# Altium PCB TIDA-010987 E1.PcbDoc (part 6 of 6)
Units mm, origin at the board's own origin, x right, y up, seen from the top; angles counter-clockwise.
Board outline 154.15 x 103.76 mm, 4 copper layers (5V, GND, MidSupply, -5V), stack 1.787 mm thick; 92 components, 52 nets, 1640 pads, 56 vias.
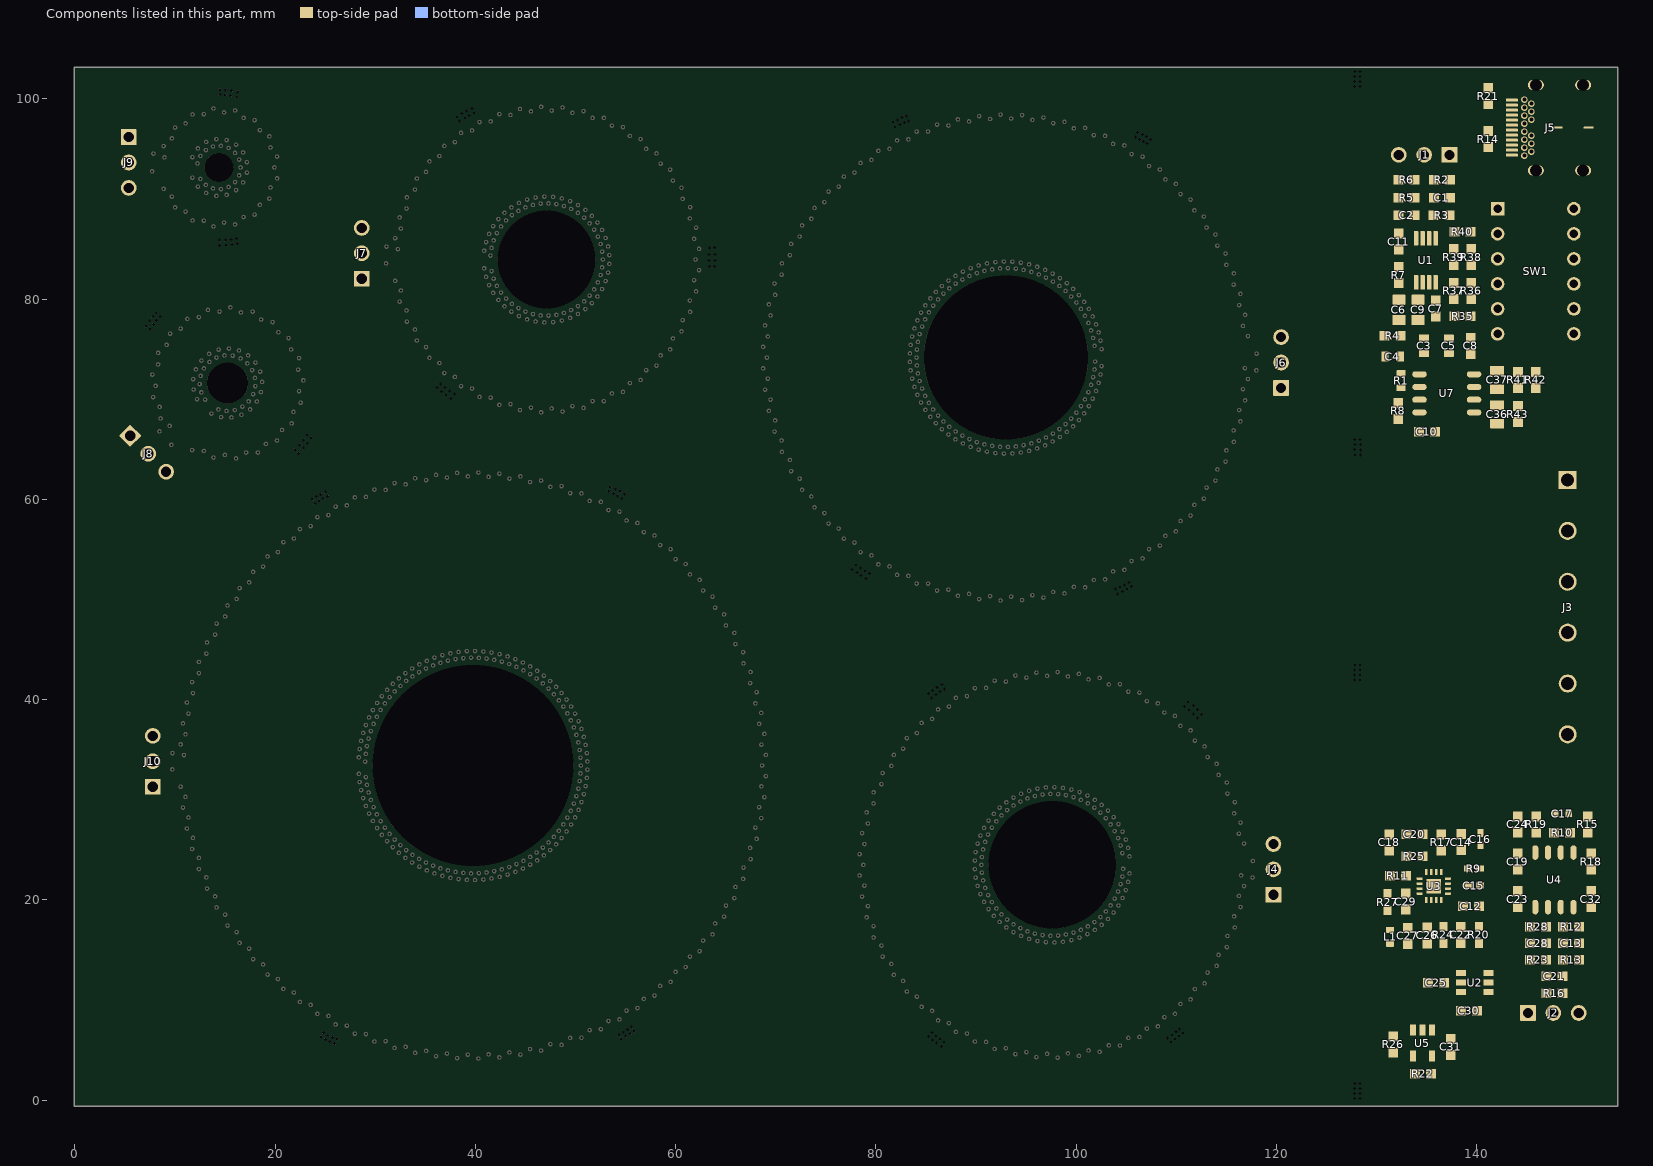
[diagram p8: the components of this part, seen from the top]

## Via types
v1: diameter 0.61, hole 0.203, 5V to -5V, tented both sides, 52 vias
v2: diameter 0.5, hole 0.2, 5V to -5V, tented both sides, 4 vias

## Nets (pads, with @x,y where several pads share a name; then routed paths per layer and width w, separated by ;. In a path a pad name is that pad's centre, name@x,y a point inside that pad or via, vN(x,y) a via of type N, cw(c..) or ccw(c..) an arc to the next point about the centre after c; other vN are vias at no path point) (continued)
copper on no net: (continued)
  -5V w0.1: 98.339,81.304 107.288,93.284 ; 98.392,66.22 106.644,54.089 ; 98.392,82.085 106.428,93.897 ccw(c106.644,94.216) 106.961,93.996 cw(c92.996,74.152) 108.064,93.172 cw(c108.364,92.931) 108.66,92.685 cw(c92.996,74.152) 109.963,91.499 ; 98.693,15.812 100.274,4.41 ; 98.693,31.173 100.221,42.194 ccw(c100.274,42.575) 100.655,42.518 cw(c97.628,23.493) 101.983,42.259 cw(c102.357,42.168) 102.73,42.07 cw(c97.628,23.493) 104.383,41.535 ; 98.95,67.501 ccw(c92.996,74.152) 99.245,67.778 cw(c99.514,68.053) 99.771,68.34 ccw(c92.996,74.152) 99.784,68.355 ccw(c100.028,68.653) 100.331,68.416 111.807,59.441 ; 98.95,80.804 ccw(c92.996,74.152) 98.642,81.067 cw(c98.339,81.304) 98.025,81.528 ccw(c92.996,74.152) 98.009,81.539 ccw(c97.686,81.748) 97.888,82.076 105.541,94.472 ; 98.987,16.537 101.248,4.963 ; 98.987,30.448 101.248,42.022 ; 99.072,66.728 108.12,55.672 ccw(c108.364,55.374) 108.064,55.133 cw(c92.996,74.152) 106.961,54.308 cw(c106.644,54.089) 106.324,53.875 cw(c92.996,74.152) 104.818,52.962 ; 99.072,81.577 108.364,92.931 ; 99.187,42.308 98.245,30.939 cw(c98.213,30.556) 98.596,30.513 cw(c97.628,23.493) 98.607,30.512 ccw(c98.987,30.448) 99.363,30.364 cw(c97.628,23.493) 99.744,30.257 ; 99.514,68.053 110.433,57.836 ; 99.514,80.252 110.433,90.469 ; 99.532,31.009 102.357,42.168 ; 99.704,67.294 109.963,56.806 ; 99.704,81.011 109.694,91.224 ccw(c109.963,91.499) 110.237,91.228 cw(c92.996,74.152) 111.177,90.222 cw(c111.43,89.932) 111.678,89.637 cw(c92.996,74.152) 112.753,88.241 ; 99.744,16.729 ccw(c97.628,23.493) 100.119,16.857 cw(c100.475,17.002) 100.823,17.167 ccw(c97.628,23.493) 100.833,17.172 ccw(c101.172,17.355) 101.364,17.022 107.068,7.142 ; 99.859,30.624 cw(c99.744,30.257) 100.108,30.132 cw(c97.628,23.493) 100.119,30.128 ccw(c100.475,29.983) 100.823,29.819 cw(c97.628,23.493) 101.172,29.63 ; 99.859,30.624 103.264,41.512 ; 100.028,68.653 ccw(c92.996,74.152) 100.27,68.978 cw(c100.486,69.296) 100.689,69.624 ccw(c92.996,74.152) 100.699,69.641 ccw(c100.886,69.977) 101.227,69.797 114.103,62.983 ; 100.028,79.652 ccw(c92.996,74.152) 99.771,79.965 cw(c99.514,80.252) 99.245,80.527 ccw(c92.996,74.152) 99.231,80.541 ccw(c98.95,80.804) 99.207,81.091 108.923,91.946 ; 100.284,67.914 111.138,58.624 ccw(c111.43,58.373) 111.177,58.083 cw(c92.996,74.152) 110.237,57.077 cw(c109.963,56.806) 109.686,56.539 cw(c92.996,74.152) 108.364,55.374 ; 100.284,80.391 111.43,89.932 ; 100.347,16.231 104.383,5.451 ; 100.347,30.754 104.248,41.174 ccw(c104.383,41.535) 104.742,41.396 cw(c97.628,23.493) 105.982,40.852 cw(c106.327,40.682) 106.669,40.505 cw(c97.628,23.493) 108.165,39.621 ; 100.475,17.002 105.212,6.203 ; 100.475,29.983 105.212,40.782 ; 100.486,69.296 113.033,61.161 ; 100.486,79.009 113.033,87.144 ; 100.807,68.583 112.753,60.064 ; 100.807,79.722 112.439,88.017 ccw(c112.753,88.241) 112.974,87.926 cw(c92.996,74.152) 113.723,86.77 cw(c113.92,86.44) 114.113,86.106 cw(c92.996,74.152) 114.924,84.542 ; 100.886,69.977 ccw(c92.996,74.152) 101.068,70.339 cw(c101.224,70.691) 101.366,71.049 ccw(c92.996,74.152) 101.373,71.068 ccw(c101.498,71.432) 101.865,71.314 115.74,66.874 ; 100.886,78.328 ccw(c92.996,74.152) 100.689,78.681 cw(c100.486,79.009) 100.27,79.327 ccw(c92.996,74.152) 100.258,79.343 ccw(c100.028,79.652) 100.331,79.889 111.807,88.864 ; 101.129,16.574 106.153,6.647 ccw(c106.327,6.303) 105.982,6.133 cw(c97.628,23.493) 104.742,5.589 cw(c104.383,5.451) 104.021,5.319 cw(c97.628,23.493) 102.357,4.817 ; 101.129,30.411 106.327,40.682 ; 101.172,17.355 ccw(c97.628,23.493) 101.509,17.563 cw(c101.826,17.782) 102.129,18.018 ccw(c97.628,23.493) 102.138,18.025 ccw(c102.428,18.278) 102.689,17.995 110.415,9.602 ; 101.224,70.691 115.008,64.892 ; 101.224,77.614 115.008,83.413 ; 101.269,69.295 113.588,62.06 ccw(c113.92,61.865) 113.723,61.535 cw(c92.996,74.152) 112.974,60.379 cw(c112.753,60.064) 112.527,59.752 cw(c92.996,74.152) 111.43,58.373 ; 101.269,79.01 113.92,86.44 ; 101.364,29.964 cw(c101.172,29.63) 101.5,29.429 cw(c97.628,23.493) 101.509,29.423 ccw(c101.826,29.203) 102.129,28.967 cw(c97.628,23.493) 102.428,28.707 ; 101.364,29.964 107.068,39.843 ; 101.498,71.432 ccw(c92.996,74.152) 101.613,71.82 cw(c101.705,72.194) 101.782,72.571 ccw(c92.996,74.152) 101.785,72.591 ccw(c101.844,72.971) 102.226,72.92 116.666,70.992 ; 101.498,76.873 ccw(c92.996,74.152) 101.366,77.256 cw(c101.224,77.614) 101.068,77.966 ccw(c92.996,74.152) 101.059,77.984 ccw(c100.886,78.328) 101.227,78.508 114.103,85.322 ; 101.666,70.045 114.924,63.763 ; 101.666,78.26 114.577,84.377 ccw(c114.924,84.542) 115.087,84.193 cw(c92.996,74.152) 115.621,82.924 cw(c115.757,82.564) 115.887,82.201 cw(c92.996,74.152) 116.411,80.519 ; 101.705,72.194 116.294,68.912 ; 101.705,76.111 116.294,79.393 ; 101.826,17.782 108.81,8.28 ; 101.826,29.203 108.81,38.705 ; 101.844,72.971 ccw(c92.996,74.152) 101.889,73.373 cw(c101.914,73.758) 101.923,74.143 118.031,74.152 120.037,73.843 ; 101.844,75.334 ccw(c92.996,74.152) 101.782,75.734 cw(c101.705,76.111) 101.613,76.485 ccw(c92.996,74.152) 101.608,76.504 ccw(c101.498,76.873) 101.865,76.991 115.74,81.431 ; 101.869,17.001 108.165,7.365 ; 101.869,29.984 107.955,39.298 ccw(c108.165,39.621) 108.485,39.407 cw(c97.628,23.493) 109.576,38.605 cw(c109.875,38.364) 110.17,38.116 cw(c97.628,23.493) 111.437,36.926 ; 101.914,73.758 116.853,73.096 ; 101.995,70.827 115.396,65.875 ccw(c115.757,65.741) 115.621,65.381 cw(c92.996,74.152) 115.087,64.112 cw(c114.924,63.763) 114.757,63.416 cw(c92.996,74.152) 113.92,61.865 ; 101.995,77.478 115.757,82.564 ; 102.254,71.635 116.411,67.786 ; 102.254,76.67 116.04,80.418 ccw(c116.411,80.519) 116.509,80.147 cw(c92.996,74.152) 116.811,78.803 cw(c116.882,78.425) 116.947,78.045 cw(c92.996,74.152) 117.166,76.297 ; 102.428,18.278 ccw(c97.628,23.493) 102.712,18.555 cw(c102.973,18.838) 103.218,19.135 ccw(c97.628,23.493) 103.224,19.144 ccw(c103.452,19.454) 103.769,19.235 113.143,12.735 ; 102.44,72.463 116.503,69.948 ccw(c116.882,69.88) 116.811,69.502 cw(c92.996,74.152) 116.509,68.158 cw(c116.411,67.786) 116.307,67.415 cw(c92.996,74.152) 115.757,65.741 ; 102.44,75.842 116.882,78.425 ; 102.552,73.305 117.166,72.008 ; 102.552,75 116.783,76.263 ccw(c117.166,76.297) 117.197,75.913 cw(c92.996,74.152) 117.238,75.226 101.914,74.547 ccw(c92.996,74.152) 101.887,74.951 ccw(c101.844,75.334) 102.226,75.385 116.666,77.313 ; 102.558,17.507 109.631,8.919 ccw(c109.875,8.622) 109.576,8.38 cw(c97.628,23.493) 108.485,7.578 cw(c108.165,7.365) 107.841,7.157 cw(c97.628,23.493) 106.327,6.303 ; 102.558,29.478 109.875,38.364 ; 102.973,18.838 111.866,11.093 ; 102.973,28.147 111.866,35.892 ; 103.186,18.086 111.437,10.059 ; 103.186,28.9 111.161,36.658 ccw(c111.437,36.926) 111.703,36.647 cw(c97.628,23.493) 112.592,35.627 cw(c112.831,35.325) 113.064,35.019 cw(c97.628,23.493) 114.04,33.581 ; 103.452,19.454 ccw(c97.628,23.493) 103.669,19.786 cw(c103.861,20.12) 104.035,20.463 ccw(c97.628,23.493) 104.04,20.473 ccw(c104.194,20.826) 104.551,20.681 115.12,16.388 ; 103.452,27.531 ccw(c97.628,23.493) 103.218,27.85 cw(c102.973,28.147) 102.712,28.431 ccw(c97.628,23.493) 102.704,28.439 ccw(c102.428,28.707) 102.689,28.99 110.415,37.383 ; 103.747,18.73 112.527,11.896 ccw(c112.831,11.66) 112.592,11.358 cw(c97.628,23.493) 111.703,10.338 cw(c111.437,10.059) 111.166,9.786 cw(c97.628,23.493) 109.875,8.622 ; 103.747,28.255 112.831,35.325 ; 103.861,20.12 114.233,14.507 ; 103.861,26.866 114.233,32.479 ; 104.194,20.826 ccw(c97.628,23.493) 104.333,21.197 cw(c104.448,21.564) 104.543,21.937 ccw(c97.628,23.493) 104.545,21.948 ccw(c104.619,22.326) 104.998,22.263 116.251,20.385 ; 104.194,26.16 ccw(c97.628,23.493) 104.035,26.522 cw(c103.861,26.866) 103.669,27.199 ccw(c97.628,23.493) 103.663,27.209 ccw(c103.452,27.531) 103.769,27.75 113.143,34.251 ; 104.234,19.432 114.04,13.404 ; 104.234,27.553 113.712,33.38 ccw(c114.04,33.581) 114.239,33.251 cw(c97.628,23.493) 114.883,32.061 cw(c115.051,31.714) 115.211,31.365 cw(c97.628,23.493) 115.849,29.748 ; 104.448,21.564 115.796,18.355 ; 104.448,25.421 115.796,28.63 ; 104.619,22.326 ccw(c97.628,23.493) 104.673,22.719 cw(c104.705,23.102) 104.715,23.487 117.663,23.493 119.71,23.038 117.66,23.878 ; 104.619,24.659 ccw(c97.628,23.493) 104.543,25.048 cw(c104.448,25.421) 104.333,25.789 ccw(c97.628,23.493) 104.33,25.799 ccw(c104.194,26.16) 104.551,26.304 115.12,30.597 ; 104.641,20.183 114.702,15.435 ccw(c115.051,15.271) 114.883,14.924 cw(c97.628,23.493) 114.239,13.734 cw(c114.04,13.404) 113.836,13.078 cw(c97.628,23.493) 112.831,11.66 ; 104.641,26.802 115.051,31.714 ; 104.705,23.102 116.48,22.453 ; 104.962,20.975 115.849,17.237 ; 104.962,26.01 115.485,29.623 ccw(c115.849,29.748) 115.971,29.383 cw(c97.628,23.493) 116.339,28.08 cw(c116.427,27.706) 116.507,27.329 cw(c97.628,23.493) 116.776,25.612 ; 105.195,21.797 116.051,19.364 ccw(c116.427,19.28) 116.339,18.905 cw(c97.628,23.493) 115.971,17.603 cw(c115.849,17.237) 115.721,16.874 cw(c97.628,23.493) 115.051,15.271 ; 105.195,25.188 116.427,27.706 ; 105.335,22.64 116.776,21.373 ; 105.335,24.346 116.394,25.57 ccw(c116.776,25.612) 116.815,25.229 cw(c97.628,23.493) 116.864,24.554 104.705,23.883 ccw(c97.628,23.493) 104.672,24.278 ccw(c104.619,24.659) 104.998,24.723 116.251,26.6 ; 116.427,19.28 ccw(c97.628,23.493) 116.73,20.991 ; 116.687,20.999 ccw(c116.776,21.373) 116.815,21.756 ccw(c97.628,23.493) 116.875,22.656 117.644,22.614 cw(c97.628,23.493) 117.623,22.229 ; 116.882,69.88 ccw(c92.996,74.152) 117.129,71.625 ; 117.095,71.63 ccw(c117.166,72.008) 117.197,72.392 ccw(c92.996,74.152) 117.246,73.304 118.016,73.27 cw(c92.996,74.152) 117.999,72.885 ; 118.028,74.537 120.037,73.843 ; 120.422,73.71 120.037,73.843 ; 120.472,73.66 120.431,73.716 120.377,73.791 120.037,73.843 ; 8.325,33.614 7.798,33.833 7.918,33.672 8.325,33.614

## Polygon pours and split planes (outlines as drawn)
-5V on -5V "-5V_-5V_P003" (solid, remove dead copper, pour order 3): 131.902,101.6 152.043,101.6 153.499,100.144 153.497,2.455 151.59,0.548 130.596,0.549 129.363,1.782 129.363,100.326 130.636,101.6
MidSupply on MidSupply "MIDSUPPLY_MIDSUPPLY_P002" (solid, remove dead copper, pour order 2): 131.902,101.6 152.043,101.6 153.499,100.144 153.497,2.461 151.584,0.548 130.596,0.549 129.363,1.782 129.363,100.326 130.636,101.6
GND on GND "GND_GND_P001" (solid, remove dead copper, pour order 1): 131.902,101.6 152.044,101.6 153.505,100.139 153.503,2.461 151.689,0.647 130.497,0.648 129.363,1.782 129.363,100.326 130.636,101.6
5V on 5V "5V_5V_P000" (solid, remove dead copper, pour order 0): 131.902,101.6 152.043,101.6 153.499,100.144 153.497,2.455 151.59,0.548 130.596,0.549 129.363,1.782 129.363,100.326 130.636,101.6

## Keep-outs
Keep-Out Layer:
  text ".Layer_Name" at 18.111,-20.282 h1.52

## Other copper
5V:
  text ".Layer_Name" at 18.111,-20.282 h1.52
-5V:
  text ".Layer_Name" at 18.111,-20.282 h1.52

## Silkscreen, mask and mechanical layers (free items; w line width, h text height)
Top Overlay:
  text "20 A" at 9.998,91.944 h0.76 r90
  text "G=1,83,133,314,667,728,1000" at 152.102,91.782 h0.76 r270
  text "1000V/V" at 10.97,91.264 h0.76 r90
  text "100 A" at 36.252,80.138 h1.52 r90
  text "667V/V" at 39.043,79.273 h1.52 r90
  text "133V/V" at 110.188,78.263 h1.52 r270
  text "250 A" at 112.981,77.817 h1.52 r270
  text "723V/V" at 13.4,66.904 h0.76 r135
  text "HW gain+int" at 138.107,66.632 h0.76 r315
  text "30 A" at 12.269,66.351 h0.76 r135
  text "HW gain" at 139.718,60.221 h0.76 r315
  text "TIDA-010987" at 130.263,59.399 h1.52 r270
  text "HW int" at 140.048,55 h0.76 r315
  text "LOG Amp 1MHz" at 137.313,53.028 h0.76 r315
  text "5KHz - 50KHz" at 136.813,47.863 h0.76 r315
  text "GND" at 143.428,34.95 h0.76 r90
  text "83V/V" at 18.791,30.873 h1.52 r90
  text "300 A" at 15.35,30.77 h1.52 r90
  text "314V/V" at 110.536,26.849 h1.52 r270
  text "160 A" at 113.397,26.3 h1.52 r270
  text ".Layer_Name" at 18.111,-20.282 h1.52
Bottom Overlay:
  text ".Layer_Name" at 18.111,-20.282 h1.52
Top Paste:
  text ".Layer_Name" at 18.111,-20.282 h1.52
Bottom Paste:
  text ".Layer_Name" at 18.111,-20.282 h1.52
Top Solder:
  text ".Layer_Name" at 18.111,-20.282 h1.52
  text ".Layer_Name" at 18.111,-20.282 h1.52
Bottom Solder:
  text ".Layer_Name" at 18.111,-20.282 h1.52
Drill Guide:
  text ".Layer_Name" at 18.111,-20.282 h1.52
M1 Board Outline:
  lines w0.254: -0.051,103.124 0,-0.635 154.098,-0.508 154.098,103.124 -0.051,103.124
  lines w0.762: 6.885,76.519 ccw(c15.261,71.606) 5.793,69.449 2.352,66.018 8.817,59.491 11.843,62.516 ccw(c15.261,71.606) 21.596,64.245 ; 8.927,78.966 cw(c15.261,71.606) 20.623,79.702 ; 13.697,85.646 cw(c14.398,93.14) 8.091,89.034 2.77,89.034 2.814,98.221 8.838,98.212 cw(c14.398,93.14) 13.704,100.633 ; 16.924,86.05 ccw(c14.398,93.14) 21.729,94.843 ; 16.924,100.229 cw(c14.398,93.14) 21.796,94.522 ; 20.057,80.049 cw(c15.261,71.606) 23.792,66.965 ; 23.213,59.374 ccw(c39.771,33.412) 9.388,38.419 5.305,38.426 5.261,29.239 9.264,29.239 ccw(c39.771,33.412) 24.055,6.934 ; 25.813,60.86 cw(c39.771,33.412) 52.678,61.369 ; 26.74,5.515 ccw(c39.771,33.412) 53.762,5.984 ; 35.798,71.867 cw(c47.117,83.947) 31.04,80.004 26.029,80.004 26.073,89.191 31.41,89.175 cw(c47.117,83.947) 37.687,97.553 ; 38.382,69.885 ccw(c47.117,83.947) 63.607,82.492 ; 40.496,99.119 cw(c47.117,83.947) 63.559,85.868 ; 55.435,59.929 cw(c39.771,33.412) 70.528,34.992 ; 56.389,7.483 ccw(c39.771,33.412) 70.513,35.261 ; 77.263,53.683 cw(c92.996,74.152) 67.204,75.294 cw(c92.996,74.152) 81.138,97.085 ; 79.835,51.942 ccw(c92.996,74.152) 103.328,50.492 ; 83.862,98.3 cw(c92.996,74.152) 105.388,96.802 ; 84.785,39.935 ccw(c97.628,23.493) 84.807,7.033 ; 87.312,5.185 ccw(c97.628,23.493) 108.631,5.589 ; 87.387,41.67 cw(c97.628,23.493) 110.415,39.979 ; 106.066,51.888 ccw(c92.996,74.152) 118.305,69.053 122.99,69.066 123.034,78.254 118.481,78.284 ccw(c92.996,74.152) 107.851,95.268 ; 111.123,7.384 ccw(c97.628,23.493) 118.029,18.451 122.228,18.444 122.272,27.631 118.078,27.631 ccw(c97.628,23.493) 112.837,37.775 ; 128.092,2.429 128.092,21.44 128.092,41.204 ; 128.092,44.238 128.092,63.662 ; 128.092,66.747 128.092,83.828 128.092,100.417
  text ".Layer_Name" at 18.111,-20.282 h1.52
M2 Board Dimensions:
  rectangle: 3.455,-5.461 6.63,-2.286
  rectangle: 6.63,-8.636 16.155,-5.461
  lines w0.178: 3.455,-5.461 28.855,-5.461 ; 6.63,-8.636 6.63,-2.286 ; 9.805,-8.636 9.805,-2.286 ; 16.155,-8.636 16.155,-2.286 ; 22.505,-8.636 22.505,-2.286 ; 3.455,-8.636 28.855,-8.636 28.855,-2.286 3.455,-2.286 3.455,-8.636
  text ".Layer_Name" at 18.111,-20.282 h1.52
M3 3D STEP Top:
  text ".Layer_Name" at 18.111,-20.282 h1.52
M4 3D STEP Bottom:
  text ".Layer_Name" at 18.111,-20.282 h1.52
M5 Assembly Top:
  lines w0.254: -3.962,-22.102 163.678,-22.102 ; -3.962,-16.938 163.729,-16.938 ; -3.962,-11.773 -3.962,-27.267 97.765,-27.267 163.729,-27.267 163.729,-11.773 -3.949,-11.773 -3.949,-27.267 36.068,-27.267 ; 58.649,-27.267 58.649,-11.773 ; 90.831,-16.938 90.831,-11.773 ; 112.167,-16.938 112.167,-11.773 ; 127.966,-27.432 127.966,-22.28
  text "COMPONENTS MARKED 'DNP' SHOULD NOT BE POPULATED." at 32.754,-6.566 h1.52
  text "ASSEMBLY VARIANT:" at 32.741,-9.5 h1.52
  text ".VariantName" at 59.055,-9.5 h1.52
  text "PCB VIEWED FROM TOP SIDE" at -2.349,-15.13 h1.52
  text "BOARD #:" at 60.554,-15.13 h1.52
  text ".PRJ_Number" at 74.41,-15.13 h1.52
  text "REV:" at 95.86,-15.13 h1.52
  text ".PCB_Rev" at 103.264,-15.13 h1.52
  text "SVN REV:" at 117.145,-15.13 h1.52
  text ".VersionControl_RevNumber" at 129.998,-15.13 h1.52
  text "TID #:" at 60.554,-20.295 h1.52
  text ".TID" at 74.41,-20.295 h1.52
  text "PLOT NAME =" at -2.349,-25.51 h1.52
  text ".plot_File_Name" at 18.111,-25.51 h1.52
  text "GENERATED    :" at 60.605,-25.51 h1.52
  text ".Print_Date" at 82.69,-25.51 h1.52
  text ".Print_Time" at 101.207,-25.51 h1.52
  text "TEXAS INSTRUMENTS" at 133.325,-25.51 h1.52
M6 Assembly Bottom:
  lines w0.254: -3.975,-16.95 163.716,-16.95 ; -3.924,-22.115 163.716,-22.115 ; 31.789,-27.445 31.789,-22.293 ; 47.587,-16.95 47.587,-11.786 ; 68.923,-16.95 68.923,-11.786 ; 101.105,-27.28 101.105,-11.786 ; 123.686,-27.28 163.703,-27.28 163.703,-11.786 -3.975,-11.786 -3.975,-27.28 61.989,-27.28 163.716,-27.28 163.716,-11.786
  text "COMPONENTS MARKED 'DNP' SHOULD NOT BE POPULATED." at 158.446,-6.553 h1.52
  text ".VariantName" at 131.928,-9.5 h1.52
  text "ASSEMBLY VARIANT:" at 158.319,-9.5 h1.52
  text ".VersionControl_RevNumber" at 29.757,-15.143 h1.52
  text "SVN REV:" at 42.609,-15.143 h1.52
  text ".PCB_Rev" at 56.49,-15.143 h1.52
  text "REV:" at 63.894,-15.143 h1.52
  text ".PRJ_Number" at 85.344,-15.143 h1.52
  text "BOARD #:" at 99.2,-15.143 h1.52
  text "PCB VIEWED FROM BOTTOM SIDE" at 162.103,-15.143 h1.52
  text ".TID" at 85.344,-20.307 h1.52
  text "TID #:" at 99.2,-20.307 h1.52
  text "TEXAS INSTRUMENTS" at 26.429,-25.523 h1.52
  text ".Print_Time" at 58.547,-25.523 h1.52
  text ".Print_Date" at 77.064,-25.523 h1.52
  text "GENERATED    :" at 99.149,-25.523 h1.52
  text ".plot_File_Name" at 141.644,-25.523 h1.52
  text "PLOT NAME =" at 162.103,-25.523 h1.52
M9 Title Sheet:
  drawing of 57 lines, arcs and shapes, not listed
  text "1" at 22.247,205.651 h1.78
  text "2" at 85.637,205.651 h1.78
  text "3" at 148.866,205.651 h1.78
  text "4" at 212.535,205.651 h1.78
  text "5" at 276.01,205.651 h1.78
  text "6" at 339.637,205.651 h1.78
  text "A" at -7.124,176.619 h1.78
  text "A" at 368.796,176.619 h1.78
  text "B" at -7.124,116.167 h1.78
  text "B" at 368.796,116.167 h1.78
  text "C" at -7.124,55.842 h1.78
  text "C" at 368.796,55.842 h1.78
  text "PROJECT TITLE:" at 291.58,8.572 h1.14
  text ".PRJ_Title" at 292.85,5.186 h1.78
  text "DESIGNED FOR:" at 291.58,0.927 h1.14
  text ".PRJ_Customer" at 292.85,-2.629 h1.78
  text "D" at -7.124,-4.356 h1.78
  text "D" at 368.796,-4.356 h1.78
  text "FILE NAME:" at 291.58,-6.693 h1.14
  text ".PCB_File_Name_No_Path" at 292.85,-9.741 h1.78
  text "Texas Instruments (TI) and/or its licensors do not warrant the accuracy or completeness of this specification" at 165.354,-13.852 h1.14
  text "ENGINEER:" at 291.58,-14.059 h1.14
  text "LAYOUT BY:" at 329.807,-14.059 h1.14
  text "or any information contained therein. TI and/or its licensors do not warrant that this design will meet" at 164.212,-16.713 h1.14
  text ".PRJ_Engineer" at 292.85,-17.996 h1.78
  text ".PCB_Layout" at 331.089,-17.996 h1.78
  text "the specifications, will be suitable for your application or fit for any particular purpose, or will operate in" at 164.212,-19.575 h1.14
  text ".Layer_Name" at 18.111,-20.282 h1.52
  text "ALTIUM DESIGNER VERSION:" at 329.807,-21.933 h1.14
  text "an implementation. TI and/or its licensors do not warrant that the design is production worthy. You should" at 164.212,-22.437 h1.14
  text "completely validate and test your design implementation to confirm the system functionality for your application." at 165.354,-25.298 h1.14
  text ".print_Scale" at 292.85,-25.319 h1.78
  text ".Application_BuildNumber" at 331.089,-25.319 h1.78
  text "1" at 22.247,-30.569 h1.78
  text "2" at 85.637,-30.569 h1.78
  text "3" at 148.866,-30.569 h1.78
  text "4" at 212.535,-30.569 h1.78
  text "5" at 276.01,-30.569 h1.78
  text "6" at 339.637,-30.569 h1.78
M10 Fab Notes:
  drawing of 189 lines, arcs and shapes, not listed
  text "DESIGN INFORMATION" at 317.958,162.971 h1.52
  text "MIN. TRACK WIDTH:" at 301.586,159.615 h1.52
  text "8" at 329.431,159.615 h1.52
  text "MIL" at 333.362,159.615 h1.52
  text "7.874" at 325.205,156.524 h1.52
  text "MIN. CLEARANCE:" at 301.586,156.462 h1.52
  text "MIL" at 333.362,156.462 h1.52
  text "MIN. VIA PAD SIZE:" at 301.586,153.309 h1.52
  text "24" at 328.669,153.309 h1.52
  text "MIL" at 333.362,153.309 h1.52
  text "0.05mm (2MIL)" at 319.239,150.01 h1.52
  text "MINIMUM ANNULAR RING" at 293.224,149.801 h1.52
  text "EXTERNAL" at 337.223,149.801 h1.52
  text "PER" at 298.304,147.004 h1.52
  text "IPC-D-275 CLASS 2 LEVEL C" at 303.892,147.004 h1.52
  text "MIL, HOLES" at 341.693,144.452 h1.52
  text "+/-" at 331.724,144.233 h1.52
  text "+/-" at 353.416,144.233 h1.52
  text "REGISTRATION TOLERANCES:" at 293.224,144.206 h1.52
  text "METAL" at 323.698,144.206 h1.52
  text "5" at 338.334,144.207 h1.52
  text "3" at 359.492,144.207 h1.52
  text "MIL" at 362.445,144.206 h1.52
  text "HOLE SIZE TOLERANCE (UNLESS OTHERWISE SPECIFIED):" at 293.224,141.709 h1.52
  text "+/-" at 353.416,141.636 h1.52
  text "3" at 359.492,141.609 h1.52
  text "MIL" at 362.445,141.609 h1.52
  text "MATERIAL:" at 291.325,138.113 h1.52
  text "FR-4 High Tg" at 316.38,134.848 h1.52
  text "X" at 312.712,134.646 h1.52
  text "FR-4" at 302.018,134.531 h1.52
  text "OTHER" at 339.813,134.531 h1.52
  text "62 MIL (1.6mm) +/-10%" at 310.149,130.898 h1.52
  text "X" at 307.098,130.836 h1.52
  text "THICKNESS:" at 293.224,130.689 h1.52
  text "OTHER" at 342.785,130.689 h1.52
  text "TOLERANCE:" at 293.224,127.176 h1.52
  text "X" at 314.769,127.176 h1.52
  text "ANSI IPC-6012 TYPE 3 CLASS 2" at 319.291,127.176 h1.52
  text "OTHER +/-" at 319.29,123.513 h1.52
  text "BOW & TWIST:" at 293.224,119.826 h1.52
  text "X" at 314.769,119.826 h1.52
  text "ANSI IPC-6012 TYPE 3 CLASS 2" at 319.291,119.826 h1.52
  text "OTHER +/-" at 319.29,116.1 h1.52
  text "DRILLING:" at 291.325,112.782 h1.52
  text "NC_DRILL FILES" at 336.054,110.11 h1.52
  text "REFERENCE:" at 293.224,110.01 h1.52
  text "X" at 309.918,110.008 h1.52
  text "AS SHOWN" at 314.439,110.01 h1.52
  text "X" at 332.803,110.01 h1.52
  text "OTHER" at 343.623,106.397 h1.52
  text "PTH COPPER THICKNESS:" at 293.216,106.307 h1.52
  text "X" at 322.152,106.307 h1.52
  text "20-30 um" at 325.403,106.307 h1.52
  text "BOARD FINISH:" at 291.325,102.558 h1.52
  text "SILKSCREEN:" at 295.267,99.761 h1.52
  text "X" at 319.595,99.761 h1.52
  text "TOP" at 322.567,99.761 h1.52
  text "X" at 332.549,99.761 h1.52
  text "BOTTOM" at 335.546,99.761 h1.52
  text "SILKSCREEN COLOR:" at 295.267,95.819 h1.52
  text "X" at 319.57,95.819 h1.52
  text "WHITE" at 322.567,95.819 h1.52
  text "OTHER" at 335.546,95.819 h1.52
  text "X" at 322.897,92.176 h1.52
  text "GREEN" at 325.894,92.176 h1.52
  text "OTHER" at 341.591,92.176 h1.52
  text "SOLDER RESIST COLOR:" at 295.267,92.001 h1.52
  text "X" at 322.897,88.258 h1.52
  text "MATTE" at 325.894,88.258 h1.52
  text "SEMI-GLOSS" at 341.58,88.241 h1.52
  text "IMMERSION GOLD (ENIG)" at 318.274,83.869 h1.52
  text "ENEPIG" at 352.248,83.686 h1.52
  text "SURFACE FINISH:" at 291.325,83.66 h1.52
  text "X" at 313.753,83.66 h1.52
  text "IMM. TIN/SILVER OR EQUIV" at 299.695,80.173 h1.52
  text "OTHER" at 336.054,80.073 h1.52
  text "ARRAY/PANEL:" at 291.325,76.126 h1.52
  text "CUT AND TRIM PER M1 BOARD OUTLINE" at 318.274,75.917 h1.52
  text "N.C. ROUTE" at 318.274,72.464 h1.52
  text "X" at 335.749,72.464 h1.52
  text "V. SCORE" at 340.271,72.464 h1.52
  text "CERTIFICATION:" at 291.325,69.184 h1.52
  text "MATERIALS AND WORKMANSHIP FOR ALL PCBS" at 309.74,69.184 h1.52
  text "TO MEET OR EXCEED THE REQUIREMENTS OF:" at 309.74,66.795 h1.52
  text "X" at 300.532,63.527 h1.52
  text "ANSI IPC-A-600F CLASS ->" at 303.784,63.527 h1.52
  text "X" at 345.643,63.527 h1.52
  text "2" at 348.437,63.527 h1.52
  text "1" at 340.436,63.489 h1.52
  text "3" at 357.428,63.489 h1.52
  text "X" at 321.157,59.776 h1.52
  text "RoHS" at 324.408,59.776 h1.52
  text "OTHER" at 340.776,59.776 h1.52
  text "PER ORDER" at 350.861,59.776 h1.52
  text "ALL BOARDS MUST MEET OR EXCEED UL94-V0 REQUIREMENTS." at 292.024,55.869 h1.52
  text "PCB MUST BEAR THE UL94V-0 UL REGISTERED MATERIAL ID NUMBER" at 292.024,52.921 h1.52
  text "ADDITIONAL REQUIREMENTS:" at 291.325,48.618 h1.52
  text "MICROSECTION:" at 293.224,45.897 h1.52
  text "YES" at 316.23,45.897 h1.52
  text "REQUIRED" at 338.112,42.231 h1.52
  text "BARE BOARD ELEC. TEST:" at 293.224,42.158 h1.52
  text "NONE" at 326.39,42.158 h1.52
  text "X" at 335.114,42.158 h1.52
  text "PER ORDER" at 353.148,42.158 h1.52
  text "XX MIL VIAS REQUIRE NON-CONDUCTIVE FILL AND PLANARIZE" at 297.495,36.952 h1.5
  text "XX MIL VIAS REQUIRE CONDUCTIVE FILL AND PLANARIZE" at 297.698,34.311 h1.52
  text "OUTER XX MIL TRACES REQUIRE 50 OHM SINGLE-ENDED IMPEDANCE" at 297.673,30.161 h1.47
  text "LAYER 2 & 3 (INNER LAYERS) XX MIL WIDE, XX MIL SPACE / TRACES REQUIRE 100 OHM DIFFERENTIAL IMPEDANCE" at 297.47,24.174 h1.52
  text ".Layer_Name" at 18.111,-20.282 h1.52
M11 Gerber Information:
  lines w0.254: -3.962,-22.102 163.678,-22.102 ; -3.962,-16.938 163.729,-16.938 ; -3.962,-11.773 -3.962,-27.267 97.765,-27.267 163.729,-27.267 163.729,-11.773 -3.949,-11.773 -3.949,-27.267 36.068,-27.267 ; 58.649,-27.267 58.649,-11.773 ; 90.831,-16.938 90.831,-11.773 ; 112.167,-16.938 112.167,-11.773 ; 127.966,-27.432 127.966,-22.28
  text "ALL ARTWORK VIEWED FROM TOP SIDE" at -2.349,-15.13 h1.52
  text "BOARD #:" at 60.554,-15.13 h1.52
  text ".PRJ_Number" at 74.41,-15.13 h1.52
  text "REV:" at 95.86,-15.13 h1.52
  text ".PCB_Rev" at 103.264,-15.13 h1.52
  text "SVN REV:" at 117.145,-15.13 h1.52
  text ".VersionControl_RevNumber" at 129.998,-15.13 h1.52
  text "LAYER NAME =" at -2.349,-20.282 h1.52
  text "TID #:" at 60.554,-20.295 h1.52
  text ".TID" at 74.41,-20.295 h1.52
  text "PLOT NAME =" at -2.349,-25.51 h1.52
  text ".plot_File_Name" at 18.111,-25.51 h1.52
  text "GENERATED    :" at 60.605,-25.51 h1.52
  text ".Print_Date" at 82.69,-25.51 h1.52
  text ".Print_Time" at 101.207,-25.51 h1.52
  text "TEXAS INSTRUMENTS" at 133.325,-25.51 h1.52
M12 Stackup:
  drawing of 295 lines, arcs and shapes, not listed
  text "Layer" at 252.923,201.547 h1.52
  text "Name" at 263.335,201.547 h1.52
  text "Material" at 286.951,201.547 h1.52
  text "Thickness" at 308.789,201.547 h1.52
  text "Constant" at 325.295,201.547 h1.52
  text "Board Layer Stack" at 339.769,201.547 h1.52
  text "Top Overlay" at 263.335,198.499 h1.52
  text "Top Solder" at 263.335,195.451 h1.52
  text "Solder Resist" at 286.951,195.451 h1.52
  text "0.40mil" at 308.789,195.451 h1.52
  text "3.5" at 325.295,195.451 h1.52
  text "1" at 252.923,192.403 h1.52
  text "5V" at 263.335,192.403 h1.52
  text "1.40mil" at 308.789,192.403 h1.52
  text "Dielectric 1" at 263.335,189.355 h1.52
  text "PP-006" at 286.951,189.355 h1.52
  text "2.80mil" at 308.789,189.355 h1.52
  text "4.1" at 325.295,189.355 h1.52
  text "2" at 252.923,186.307 h1.52
  text "GND" at 263.335,186.307 h1.52
  text "CF-004" at 286.951,186.307 h1.52
  text "1.38mil" at 308.789,186.307 h1.52
  text "Dielectric1" at 263.335,183.259 h1.52
  text "FR-4 High Tg" at 286.951,183.259 h1.52
  text "59.20mil" at 308.789,183.259 h1.52
  text "4.8" at 325.295,183.259 h1.52
  text "3" at 252.923,180.211 h1.52
  text "MidSupply" at 263.335,180.211 h1.52
  text "CF-004" at 286.951,180.211 h1.52
  text "1.38mil" at 308.789,180.211 h1.52
  text "Dielectric 2" at 263.335,177.163 h1.52
  text "PP-006" at 286.951,177.163 h1.52
  text "2.80mil" at 308.789,177.163 h1.52
  text "4.1" at 325.295,177.163 h1.52
  text "4" at 252.923,174.115 h1.52
  text "-5V" at 263.335,174.115 h1.52
  text "1.40mil" at 308.789,174.115 h1.52
  text "Bottom Solder" at 263.335,171.067 h1.52
  text "Solder Resist" at 286.951,171.067 h1.52
  text "0.40mil" at 308.789,171.067 h1.52
  text "3.5" at 325.295,171.067 h1.52
  text "Bottom Overlay" at 263.335,168.019 h1.52
  text ".Layer_Name" at 18.111,-20.282 h1.52
M13 Component Bodies Top:
  text ".Layer_Name" at 18.111,-20.282 h1.52
M14 Component Bodies Bottom:
  text ".Layer_Name" at 18.111,-20.282 h1.52
M15 Courtyards Top:
  text ".Layer_Name" at 18.111,-20.282 h1.52
M16 Courtyards Bottom:
  text ".Layer_Name" at 18.111,-20.282 h1.52
Drill Drawing:
  text ".Layer_Name" at 18.111,-20.282 h1.52
M17 Embedded Cavity:
  text ".Layer_Name" at 18.111,-20.282 h1.52
M18 Embedded Assembly:
  text ".Layer_Name" at 18.111,-20.282 h1.52
M19 Embedded Keepout:
  text ".Layer_Name" at 18.111,-20.282 h1.52

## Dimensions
3.455,-8.636 to 28.855,-8.636 on M2 Board Dimensions
-0.051,-0.635 to -0.051,103.124 on M2 Board Dimensions
-0.051,-0.635 to 154.098,-0.635 on M2 Board Dimensions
